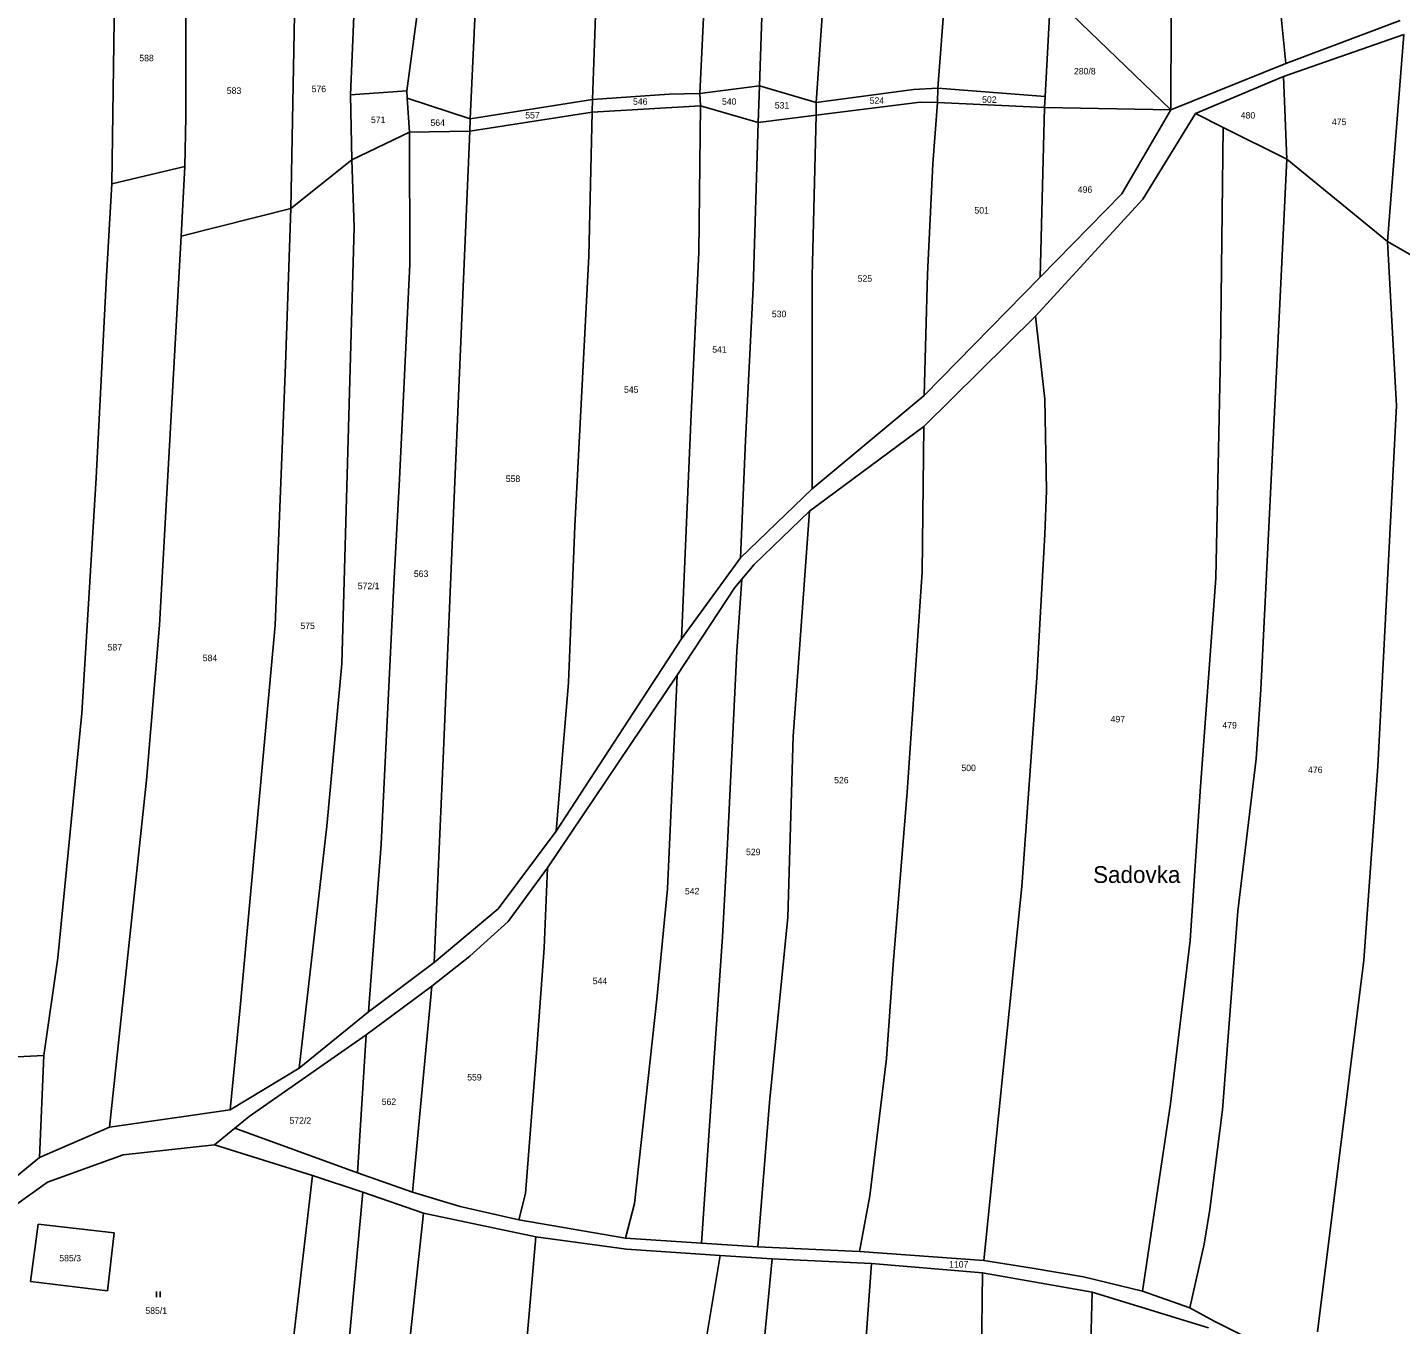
# Model space of a CAD drawing. Extents: x -794142 to -791199, y -1109267 to -1105626.
# Drawn here: x -793027.4 to -792667.2, y -1107432.6 to -1107092.4 of the extents above; entities that cross this region are included whole.
import ezdxf

# ---------------------------------------------------------------- set-up
doc = ezdxf.new("R2010")
doc.units = 0
for name, color, linetype in [('Vrstva 1', 7, 'Continuous'), ('Vrstva 14', 7, 'Continuous'), ('Vrstva 23', 7, 'Continuous'), ('Vrstva 39', 7, 'Continuous')]:
    doc.layers.add(name, color=color, linetype=linetype)

msp = doc.modelspace()

# ---------------------------------------------------------------- linework, layer by layer
at = {"layer": 'Vrstva 1'}
for p, q in [((-792879.2, -1107111.32), (-792876.78, -1107041.95)), ((-792908.04, -1107045.5), (-792911.26, -1107116.39)), ((-792848.56, -1107056.16), (-792851, -1107109.74)), ((-792816.44, -1107053.57), (-792820.51, -1107112.13)), ((-792835.35, -1107107.75), (-792833.72, -1107057.79)), ((-792784.88, -1107057.96), (-792788.58, -1107108.38)), ((-792701.16, -1107062.62), (-792697.34, -1107101.91)), ((-793005.31, -1107133.46), (-793004.33, -1107069.02)), ((-792985.85, -1107076.9), (-792985.85, -1107099.44)), ((-792957.19, -1107079.85), (-792958.29, -1107139.92)), ((-792924.69, -1107084.87), (-792927.89, -1107109.06)), ((-792758.99, -1107083.68), (-792760.46, -1107110.51)), ((-792758.99, -1107083.68), (-792727.53, -1107114.02)), ((-792942.65, -1107110.05), (-792941.77, -1107089.48)), ((-792727.41, -1107089.72), (-792727.53, -1107114.02)), ((-792697.34, -1107101.91), (-792667.31, -1107090.61)), ((-792666.34, -1107094.23), (-792697.93, -1107105.28)), ((-792666.34, -1107094.23), (-792670.66, -1107148.55)), ((-792985.85, -1107099.44), (-792985.85, -1107115.96)), ((-792727.53, -1107114.02), (-792697.34, -1107101.91)), ((-792697.93, -1107105.28), (-792721, -1107115.02)), ((-792697.93, -1107105.28), (-792697.09, -1107126.92)), ((-792927.89, -1107109.06), (-792942.65, -1107110.05)), ((-792942.65, -1107110.05), (-792942.32, -1107127.11)), ((-792927.78, -1107110.92), (-792927.89, -1107109.06)), ((-792911.26, -1107116.39), (-792927.78, -1107110.92)), ((-792927.78, -1107110.92), (-792927.23, -1107119.89)), ((-792879.2, -1107111.32), (-792859.09, -1107109.93)), ((-792859.09, -1107109.93), (-792851, -1107109.74)), ((-792851, -1107109.74), (-792835.35, -1107107.75)), ((-792851, -1107109.74), (-792850.88, -1107112.96)), ((-792835.35, -1107107.75), (-792835.78, -1107117.31)), ((-792820.51, -1107112.13), (-792835.35, -1107107.75)), ((-792820.51, -1107112.13), (-792795, -1107108.69)), ((-792795, -1107108.69), (-792788.58, -1107108.38)), ((-792788.58, -1107108.38), (-792788.69, -1107112.1)), ((-792788.58, -1107108.38), (-792760.46, -1107110.51)), ((-792760.46, -1107110.51), (-792760.64, -1107113.43)), ((-792879.32, -1107114.62), (-792911.35, -1107119.6)), ((-792879.2, -1107111.32), (-792911.26, -1107116.39)), ((-792879.32, -1107114.62), (-792880.12, -1107152.38)), ((-792879.32, -1107114.62), (-792879.2, -1107111.32)), ((-792879.32, -1107114.62), (-792850.88, -1107112.96)), ((-792850.88, -1107112.96), (-792851.32, -1107151.36)), ((-792850.88, -1107112.96), (-792835.78, -1107117.31)), ((-792820.57, -1107115.43), (-792793.28, -1107112.05)), ((-792820.51, -1107112.13), (-792820.57, -1107115.43)), ((-792793.28, -1107112.05), (-792788.69, -1107112.1)), ((-792788.69, -1107112.1), (-792789.89, -1107128.18)), ((-792788.69, -1107112.1), (-792760.64, -1107113.43)), ((-792760.64, -1107113.43), (-792761.79, -1107157.9)), ((-792760.64, -1107113.43), (-792727.53, -1107114.02)), ((-792727.53, -1107114.02), (-792740.39, -1107136.06)), ((-792985.85, -1107115.96), (-792986.17, -1107128.87)), ((-792911.26, -1107116.39), (-792911.35, -1107119.6)), ((-792837.04, -1107160.74), (-792835.78, -1107117.31)), ((-792835.78, -1107117.31), (-792820.57, -1107115.43)), ((-792820.57, -1107115.43), (-792821.57, -1107157.67)), ((-792734.87, -1107137.42), (-792721, -1107115.02)), ((-792721, -1107115.02), (-792713.78, -1107118.61)), ((-792942.32, -1107127.11), (-792927.23, -1107119.89)), ((-792927.23, -1107119.89), (-792911.35, -1107119.6)), ((-792927.23, -1107119.89), (-792927.15, -1107154.51)), ((-792911.35, -1107119.6), (-792915.47, -1107215.67)), ((-792713.78, -1107118.61), (-792714.51, -1107177.83)), ((-792713.78, -1107118.61), (-792697.09, -1107126.92)), ((-793005.31, -1107133.46), (-792986.17, -1107128.87)), ((-792986.17, -1107128.87), (-792987.05, -1107147.14)), ((-792958.29, -1107139.92), (-792942.32, -1107127.11)), ((-792942.32, -1107127.11), (-792941.72, -1107144.75)), ((-792789.89, -1107128.18), (-792791.31, -1107157.14)), ((-792697.09, -1107126.92), (-792699.1, -1107168.48)), ((-792697.09, -1107126.92), (-792670.66, -1107148.55)), ((-793005.31, -1107133.46), (-793006.66, -1107157.68)), ((-792740.39, -1107136.06), (-792761.79, -1107157.9)), ((-792987.05, -1107147.14), (-792958.29, -1107139.92)), ((-792958.29, -1107139.92), (-792959.75, -1107180.92)), ((-792763.01, -1107168.15), (-792734.87, -1107137.42)), ((-792987.05, -1107147.14), (-792992.76, -1107249.12)), ((-792941.72, -1107144.75), (-792943.07, -1107194.29)), ((-792670.66, -1107148.55), (-792651.01, -1107159.9)), ((-792670.66, -1107148.55), (-792668.29, -1107191.63)), ((-792880.12, -1107152.38), (-792883.87, -1107223.17)), ((-792851.32, -1107151.36), (-792853.32, -1107193.81)), ((-793006.66, -1107157.68), (-793009.37, -1107210.52)), ((-792927.15, -1107154.51), (-792929.85, -1107210.87)), ((-792821.57, -1107157.67), (-792821.57, -1107213.38)), ((-792791.31, -1107157.14), (-792792.2, -1107188.92)), ((-792761.79, -1107157.9), (-792792.2, -1107188.92)), ((-792839.03, -1107200.77), (-792837.04, -1107160.74)), ((-792792.29, -1107197.03), (-792763.01, -1107168.15)), ((-792763.01, -1107168.15), (-792760.51, -1107189.87)), ((-792699.1, -1107168.48), (-792703.91, -1107266.01)), ((-792714.51, -1107177.83), (-792715.68, -1107236.84)), ((-792959.75, -1107180.92), (-792962.45, -1107249.15)), ((-792792.2, -1107188.92), (-792821.57, -1107213.38)), ((-792760.51, -1107189.87), (-792760.08, -1107213.85)), ((-792853.32, -1107193.81), (-792855.84, -1107252.76)), ((-792668.29, -1107191.63), (-792673.21, -1107286.25)), ((-792943.07, -1107194.29), (-792944.95, -1107259.31)), ((-792822.3, -1107219.23), (-792792.29, -1107197.03)), ((-792792.29, -1107197.03), (-792792.76, -1107235.22)), ((-792839.03, -1107200.77), (-792840.38, -1107231.52)), ((-793009.37, -1107210.52), (-793013.12, -1107272.2)), ((-792929.85, -1107210.87), (-792931.35, -1107238.42)), ((-792821.57, -1107213.38), (-792840.38, -1107231.52)), ((-792760.08, -1107213.85), (-792760.51, -1107225.35)), ((-792915.47, -1107215.67), (-792918.41, -1107284.11)), ((-792836.75, -1107233.27), (-792822.3, -1107219.23)), ((-792822.3, -1107219.23), (-792826.57, -1107278.27)), ((-792883.87, -1107223.17), (-792885.48, -1107264.18)), ((-792760.51, -1107225.35), (-792762.65, -1107262.93)), ((-792840.38, -1107231.52), (-792855.84, -1107252.76)), ((-792840.01, -1107237.13), (-792836.75, -1107233.27)), ((-792841.85, -1107239.3), (-792840.01, -1107237.13)), ((-792841.34, -1107256.02), (-792840.01, -1107237.13)), ((-792792.76, -1107235.22), (-792796.67, -1107292.92)), ((-792715.68, -1107236.84), (-792719.75, -1107291.44)), ((-792931.35, -1107238.42), (-792934.66, -1107306.61)), ((-792856.96, -1107262.31), (-792841.85, -1107239.3)), ((-792992.76, -1107249.12), (-792996.17, -1107289.8)), ((-792962.45, -1107249.15), (-792971.62, -1107349.42)), ((-792855.84, -1107252.76), (-792888.69, -1107303.21)), ((-792843.8, -1107306.54), (-792841.34, -1107256.02)), ((-792944.95, -1107259.31), (-792948.86, -1107301.91)), ((-792890.96, -1107312.81), (-792856.96, -1107262.31)), ((-792859.53, -1107318.3), (-792856.96, -1107262.31)), ((-792885.48, -1107264.18), (-792888.69, -1107303.21)), ((-792762.65, -1107262.93), (-792766.61, -1107317.67)), ((-792703.91, -1107266.01), (-792705.09, -1107284.22)), ((-793013.12, -1107272.2), (-793019.43, -1107336.36)), ((-792826.57, -1107278.27), (-792827.96, -1107325.71)), ((-792918.41, -1107284.11), (-792920.7, -1107337.6)), ((-792705.09, -1107284.22), (-792709.9, -1107324.2)), ((-792673.21, -1107286.25), (-792676.85, -1107337.02)), ((-792996.17, -1107289.8), (-793005.93, -1107380.82)), ((-792796.67, -1107292.92), (-792800.31, -1107338.17)), ((-792719.75, -1107291.44), (-792722.42, -1107331.82)), ((-792948.86, -1107301.91), (-792956.14, -1107365.35)), ((-792888.69, -1107303.21), (-792903.97, -1107323.52)), ((-792934.66, -1107306.61), (-792937.93, -1107350.55)), ((-792845.08, -1107330.87), (-792843.8, -1107306.54)), ((-792901.36, -1107326.85), (-792890.96, -1107312.81)), ((-792891.84, -1107333.81), (-792890.96, -1107312.81)), ((-792862.31, -1107347.21), (-792859.53, -1107318.3)), ((-792766.61, -1107317.67), (-792776.51, -1107415.81)), ((-792903.97, -1107323.52), (-792920.7, -1107337.6)), ((-792911.34, -1107336), (-792901.36, -1107326.85)), ((-792827.96, -1107325.71), (-792832.78, -1107374.35)), ((-792709.9, -1107324.2), (-792713.96, -1107376.25)), ((-792848.08, -1107374.05), (-792845.08, -1107330.87)), ((-792893.87, -1107361.29), (-792891.84, -1107333.81)), ((-792722.42, -1107331.82), (-792727.56, -1107374.69)), ((-793019.43, -1107336.36), (-793023.14, -1107362.03)), ((-792920.7, -1107337.6), (-792937.93, -1107350.55)), ((-792921.32, -1107343.8), (-792911.34, -1107336)), ((-792676.85, -1107337.02), (-792689.04, -1107434.48)), ((-792800.31, -1107338.17), (-792802.07, -1107362.83)), ((-792938.57, -1107356.58), (-792921.32, -1107343.8)), ((-792921.32, -1107343.8), (-792926.4, -1107397.87)), ((-792868.2, -1107400.82), (-792862.31, -1107347.21)), ((-792971.62, -1107349.42), (-792974.27, -1107376.26)), ((-792937.93, -1107350.55), (-792956.14, -1107365.35)), ((-792969.28, -1107378.04), (-792938.57, -1107356.58)), ((-792940.82, -1107392.76), (-792938.57, -1107356.58)), ((-793050.45, -1107363.43), (-793023.14, -1107362.03)), ((-793023.14, -1107362.03), (-793024.27, -1107388.72)), ((-792896.74, -1107398.22), (-792893.87, -1107361.29)), ((-792802.07, -1107362.83), (-792806.46, -1107398.79)), ((-792956.14, -1107365.35), (-792974.27, -1107376.26)), ((-792850.62, -1107411.24), (-792848.08, -1107374.05)), ((-792974.27, -1107376.26), (-793005.93, -1107380.82)), ((-792832.78, -1107374.35), (-792835.79, -1107412.17)), ((-792727.56, -1107374.69), (-792734.94, -1107423.82)), ((-792713.96, -1107376.25), (-792717.29, -1107402.38)), ((-793005.93, -1107380.82), (-793024.27, -1107388.72)), ((-792978.37, -1107385.48), (-792973.03, -1107381.11)), ((-792973.03, -1107381.11), (-792969.28, -1107378.04)), ((-792940.82, -1107392.76), (-792973.03, -1107381.11)), ((-793002.3, -1107388.02), (-793022.12, -1107395.25)), ((-792978.37, -1107385.48), (-793002.3, -1107388.02)), ((-792952.63, -1107393.48), (-792978.37, -1107385.48)), ((-793024.27, -1107388.72), (-793050.5, -1107410.33)), ((-793022.12, -1107395.25), (-793037.81, -1107406.4)), ((-792963.78, -1107488.36), (-792952.63, -1107393.48)), ((-792952.63, -1107393.48), (-792939.43, -1107397.86)), ((-792926.4, -1107397.87), (-792940.82, -1107392.76)), ((-792939.43, -1107397.86), (-792943.16, -1107438.57)), ((-792939.43, -1107397.86), (-792923.57, -1107403.32)), ((-792913.87, -1107401.57), (-792926.4, -1107397.87)), ((-792898.53, -1107405.13), (-792896.74, -1107398.22)), ((-792806.46, -1107398.79), (-792809.14, -1107413.44)), ((-792898.53, -1107405.13), (-792913.87, -1107401.57)), ((-792870.55, -1107409.92), (-792868.2, -1107400.82)), ((-792717.29, -1107402.38), (-792718.78, -1107411.46)), ((-793026.6, -1107421.3), (-793024.56, -1107406.24)), ((-793024.56, -1107406.24), (-793004.64, -1107408.48)), ((-792923.57, -1107403.32), (-792927.57, -1107440.89)), ((-792923.57, -1107403.32), (-792894.07, -1107409.56)), ((-792870.55, -1107409.92), (-792898.53, -1107405.13)), ((-793004.64, -1107408.48), (-793006.45, -1107423.75)), ((-792894.07, -1107409.56), (-792896.64, -1107438.76)), ((-792894.07, -1107409.56), (-792870.3, -1107412.84)), ((-792850.62, -1107411.24), (-792870.55, -1107409.92)), ((-792870.3, -1107412.84), (-792845.71, -1107414.47)), ((-792835.79, -1107412.17), (-792850.62, -1107411.24)), ((-792809.14, -1107413.44), (-792835.79, -1107412.17)), ((-792776.51, -1107415.81), (-792809.14, -1107413.44)), ((-792718.78, -1107411.46), (-792722.52, -1107428.16)), ((-792845.71, -1107414.47), (-792852.48, -1107454.78)), ((-792845.71, -1107414.47), (-792832.07, -1107415.3)), ((-792832.07, -1107415.3), (-792837, -1107465.82)), ((-792832.07, -1107415.3), (-792806.02, -1107416.53)), ((-792806.02, -1107416.53), (-792811.43, -1107492.03)), ((-792806.02, -1107416.53), (-792776.89, -1107418.99)), ((-792763.88, -1107417.76), (-792776.51, -1107415.81)), ((-792776.89, -1107418.99), (-792777.21, -1107444.42)), ((-792776.89, -1107418.99), (-792748.17, -1107424.12)), ((-792750.41, -1107420.05), (-792763.88, -1107417.76)), ((-792734.94, -1107423.82), (-792750.41, -1107420.05)), ((-793006.45, -1107423.75), (-793026.6, -1107421.3)), ((-792748.17, -1107424.12), (-792749, -1107460.54)), ((-792748.17, -1107424.12), (-792717.64, -1107433.47)), ((-792722.52, -1107428.16), (-792734.94, -1107423.82)), ((-792716.09, -1107431.66), (-792722.52, -1107428.16)), ((-792689.9, -1107444.66), (-792716.09, -1107431.66))]:
    msp.add_line(p, q, dxfattribs=at)
at = {"layer": 'Vrstva 23'}
for p, q in [((-792993.56, -1107425.38), (-792993.56, -1107423.88)), ((-792992.56, -1107423.88), (-792992.56, -1107425.38))]:
    msp.add_line(p, q, dxfattribs=at)

# ---------------------------------------------------------------- texts
at = {"layer": 'Vrstva 14'}
for s, p in [('588', (-792998.073, -1107101.29)), ('280/8', (-792752.909, -1107104.74)), ('583', (-792975.123, -1107109.83)), ('576', (-792952.87, -1107109.39)), ('546', (-792868.579, -1107112.69)), ('540', (-792845.238, -1107112.69)), ('524', (-792806.509, -1107112.44)), ('502', (-792776.992, -1107112.19)), ('557', (-792896.836, -1107116.28)), ('531', (-792831.376, -1107113.68)), ('480', (-792709.162, -1107116.3)), ('571', (-792937.313, -1107117.49)), ('564', (-792921.699, -1107118.25)), ('475', (-792685.235, -1107118.03)), ('496', (-792751.913, -1107135.78)), ('501', (-792779.015, -1107141.23)), ('525', (-792809.649, -1107159.1)), ('530', (-792832.152, -1107168.4)), ('541', (-792847.792, -1107177.7)), ('545', (-792870.935, -1107188.24)), ('558', (-792901.949, -1107211.61)), ('563', (-792926.053, -1107236.52)), ('572/1', (-792940.766, -1107239.73)), ('575', (-792955.816, -1107250.18)), ('587', (-793006.389, -1107255.8)), ('584', (-792981.429, -1107258.61)), ('497', (-792743.289, -1107274.65)), ('479', (-792713.979, -1107276.26)), ('500', (-792782.431, -1107287.44)), ('476', (-792691.509, -1107287.94)), ('526', (-792815.813, -1107290.65)), ('529', (-792838.923, -1107309.48)), ('542', (-792854.949, -1107319.76)), ('544', (-792879.125, -1107343.31)), ('559', (-792912.059, -1107368.57)), ('562', (-792934.493, -1107374.99)), ('572/2', (-792958.692, -1107379.92)), ('585/3', (-793019.062, -1107416.01)), ('1107', (-792785.669, -1107417.63)), ('585/1', (-792996.476, -1107429.77))]:
    msp.add_text(s, height=1.7, dxfattribs=at).set_placement(p)
at = {"layer": 'Vrstva 39'}
msp.add_text('Sadovka', height=4.4, dxfattribs=at).set_placement((-792747.89, -1107316.76))

doc.saveas('drawing.dxf')
